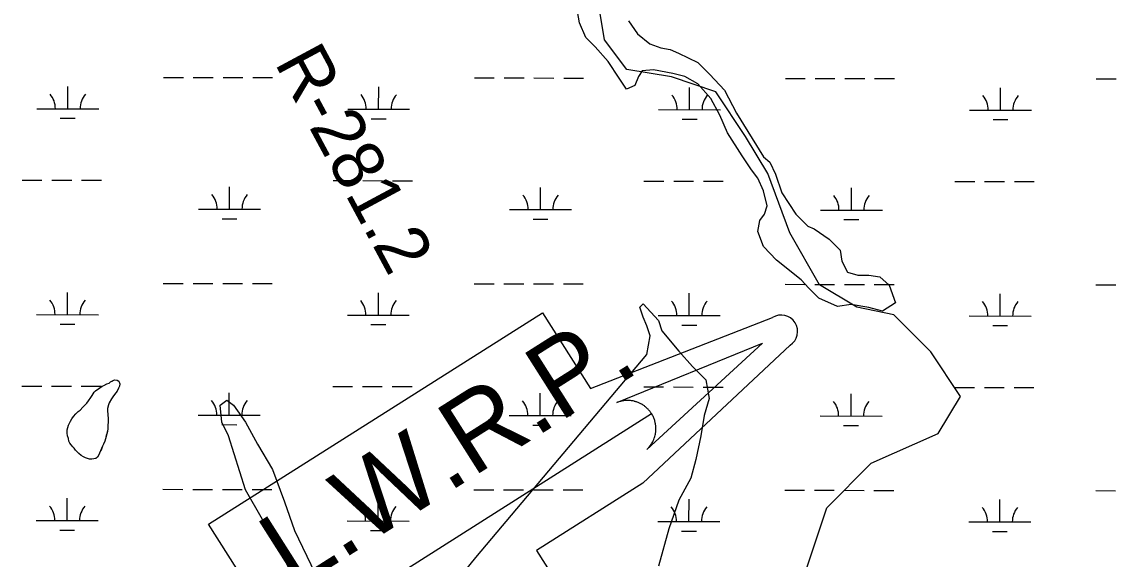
# Model space of a CAD drawing. Extents: x 3208593 to 3246461, y 812903 to 838290.
# Drawn here: x 3212819 to 3214585, y 827157 to 828025 of the extents above; entities that cross this region are included whole.
import ezdxf

# ---------------------------------------------------------------- set-up
doc = ezdxf.new("R2010")
doc.units = 0
for name, color, linetype in [('V-RIVR-RANG-IDEN', 7, 'Continuous'), ('V-SITE-VEGE', 7, 'Continuous'), ('V-TOPO-SHOR', 7, 'Continuous'), ('V-TOPO-WATR-IDEN', 7, 'Continuous'), ('V-WETL-SWMP', 7, 'Continuous')]:
    doc.layers.add(name, color=color, linetype=linetype)

msp = doc.modelspace()

# ---------------------------------------------------------------- linework, layer by layer
at = {"layer": 'V-SITE-VEGE'}
for p, q in [((3213718.7, 828023.5), (3213715.7, 828041.5)), ((3213729.1, 827999.7), (3213718.7, 828023.5)), ((3213797.8, 828026.5), (3213812.7, 828005.6)), ((3213812.7, 828005.6), (3213832.1, 827989.2)), ((3213744.1, 827984.7), (3213729.1, 827999.7)), ((3213832.1, 827989.2), (3213850, 827983.2)), ((3213765, 827960.8), (3213744.1, 827984.7)), ((3213850, 827983.2), (3213865, 827980.2)), ((3213865, 827980.2), (3213878.4, 827974.3)), ((3213878.4, 827974.3), (3213909.7, 827959.3)), ((3213782.9, 827934), (3213765, 827960.8)), ((3213909.7, 827959.3), (3213929.1, 827939.9)), ((3213814.2, 827936.9), (3213808.2, 827922)), ((3213820.2, 827945.9), (3213814.2, 827936.9)), ((3213838.1, 827947.4), (3213820.2, 827945.9)), ((3213869.4, 827941.4), (3213838.1, 827947.4)), ((3213888.8, 827936.9), (3213869.4, 827941.4)), ((3213909.7, 827925), (3213888.8, 827936.9)), ((3213929.1, 827939.9), (3213953, 827914.5)), ((3213794.8, 827916), (3213782.9, 827934)), ((3213808.2, 827922), (3213794.8, 827916)), ((3213930.6, 827901.1), (3213909.7, 827925)), ((3213945.5, 827874.2), (3213930.6, 827901.1)), ((3213953, 827914.5), (3213972.4, 827877.2)), ((3213957.5, 827845.9), (3213945.5, 827874.2)), ((3213972.4, 827877.2), (3214015.7, 827807)), ((3213981.4, 827808.5), (3213957.5, 827845.9)), ((3213996.3, 827786.1), (3213981.4, 827808.5)), ((3214015.7, 827807), (3214026.1, 827798.1)), ((3214026.1, 827798.1), (3214035.1, 827778.7)), ((3214006.7, 827772.7), (3213996.3, 827786.1)), ((3214035.1, 827778.7), (3214045.5, 827748.8)), ((3214015.7, 827751.8), (3214006.7, 827772.7)), ((3214021.7, 827727.9), (3214015.7, 827751.8)), ((3214045.5, 827748.8), (3214067.9, 827714.5)), ((3214017.2, 827714.5), (3214021.7, 827727.9)), ((3214009.7, 827704), (3214017.2, 827714.5)), ((3214067.9, 827714.5), (3214087.3, 827695)), ((3214006.7, 827686.1), (3214009.7, 827704)), ((3214087.3, 827695), (3214097.8, 827690.6)), ((3214097.8, 827690.6), (3214121.7, 827674.1)), ((3214015.7, 827662.2), (3214006.7, 827686.1)), ((3214121.7, 827674.1), (3214139.6, 827656.2)), ((3214036.6, 827639.8), (3214015.7, 827662.2)), ((3214139.6, 827656.2), (3214142.5, 827638.3)), ((3214076.9, 827608.4), (3214036.6, 827639.8)), ((3214142.5, 827638.3), (3214151.5, 827620.4)), ((3214151.5, 827620.4), (3214167.9, 827615.9)), ((3214088.8, 827595), (3214076.9, 827608.4)), ((3214167.9, 827615.9), (3214185.8, 827615.9)), ((3214185.8, 827615.9), (3214203.7, 827612.9)), ((3214203.7, 827612.9), (3214218.7, 827599.5)), ((3214218.7, 827599.5), (3214229.1, 827571.1)), ((3214105.2, 827578.6), (3214088.8, 827595)), ((3213816.4, 827564.1), (3213821.8, 827569.6)), ((3213821.8, 827547.7), (3213816.4, 827564.1)), ((3213821.8, 827569.6), (3213846.4, 827542.3)), ((3214135.1, 827565.1), (3214105.2, 827578.6)), ((3214157.5, 827568.1), (3214135.1, 827565.1)), ((3214185.8, 827563.6), (3214157.5, 827568.1)), ((3214208.2, 827557.7), (3214185.8, 827563.6)), ((3214229.1, 827571.1), (3214208.2, 827557.7)), ((3213827.3, 827534.1), (3213821.8, 827547.7)), ((3213832.7, 827517.6), (3213827.3, 827534.1)), ((3213846.4, 827542.3), (3213851.9, 827525.8)), ((3213827.3, 827487.6), (3213832.7, 827517.6)), ((3213851.9, 827525.8), (3213879.2, 827493)), ((3213879.2, 827493), (3213901.1, 827468.4)), ((3213551.3, 827159.5), (3213827.3, 827487.6)), ((3213901.1, 827468.4), (3213922.9, 827446.6)), ((3212951, 827437.5), (3212956, 827440.1)), ((3212956, 827440.1), (3212959.5, 827441.3)), ((3212959.5, 827441.3), (3212961.9, 827443.2)), ((3212961.9, 827443.2), (3212968, 827446.4)), ((3212968, 827446.4), (3212972.3, 827446.1)), ((3212972.3, 827446.1), (3212975.3, 827444.5)), ((3212975.3, 827444.5), (3212976.9, 827440.3)), ((3212976.9, 827440.3), (3212976.1, 827436.4)), ((3213922.9, 827446.6), (3213928.4, 827416.5)), ((3212932.3, 827421.4), (3212933.7, 827424.1)), ((3212933.7, 827424.1), (3212935.3, 827426.7)), ((3212935.3, 827426.7), (3212937.4, 827429.1)), ((3212937.4, 827429.1), (3212948.1, 827436.3)), ((3212948.1, 827436.3), (3212951, 827437.5)), ((3212972.4, 827428.5), (3212966.5, 827420.9)), ((3212974.8, 827433), (3212972.4, 827428.5)), ((3212976.1, 827436.4), (3212974.8, 827433)), ((3212917.2, 827402.3), (3212920.5, 827405.7)), ((3212920.5, 827405.7), (3212923.3, 827408.7)), ((3212923.3, 827408.7), (3212926.4, 827412.6)), ((3212926.4, 827412.6), (3212930.2, 827418)), ((3212930.2, 827418), (3212932.3, 827421.4)), ((3212958.5, 827406.3), (3212957.1, 827400.5)), ((3212959.5, 827409.6), (3212958.5, 827406.3)), ((3212963.2, 827416), (3212959.5, 827409.6)), ((3212966.5, 827420.9), (3212963.2, 827416)), ((3213138.7, 827405.6), (3213149.6, 827413.8)), ((3213141.4, 827378.2), (3213138.7, 827405.6)), ((3213149.6, 827413.8), (3213160.5, 827405.6)), ((3213160.5, 827405.6), (3213179.7, 827378.2)), ((3213928.4, 827416.5), (3213920.2, 827389.2)), ((3212899.5, 827383.8), (3212902.2, 827387.4)), ((3212902.2, 827387.4), (3212906, 827391.8)), ((3212906, 827391.8), (3212909.5, 827395.4)), ((3212909.5, 827395.4), (3212912.5, 827397.7)), ((3212912.5, 827397.7), (3212917.2, 827402.3)), ((3212957.1, 827400.5), (3212957.1, 827396)), ((3212957.1, 827396), (3212957.6, 827391)), ((3212957.6, 827391), (3212957.8, 827383.1)), ((3213920.2, 827389.2), (3213914.7, 827356.3)), ((3212892, 827366), (3212893.8, 827373.3)), ((3212893.8, 827373.3), (3212895.3, 827376.7)), ((3212895.3, 827376.7), (3212896.9, 827379.9)), ((3212896.9, 827379.9), (3212899.5, 827383.8)), ((3212957.6, 827373.2), (3212957.3, 827367.3)), ((3212957.8, 827378.2), (3212957.6, 827373.2)), ((3212957.8, 827383.1), (3212957.8, 827378.2)), ((3213152.4, 827356.3), (3213141.4, 827378.2)), ((3213179.7, 827378.2), (3213198.8, 827342.7)), ((3212891.7, 827360.3), (3212892, 827366)), ((3212892.3, 827356.3), (3212891.7, 827360.3)), ((3212893.9, 827351.8), (3212892.3, 827356.3)), ((3212894.7, 827347.6), (3212893.9, 827351.8)), ((3212953.6, 827351.5), (3212952.4, 827347.7)), ((3212956.9, 827363.9), (3212953.6, 827351.5)), ((3212957.3, 827367.3), (3212956.9, 827363.9)), ((3213179.7, 827268.9), (3213152.4, 827356.3)), ((3213914.7, 827356.3), (3213906.5, 827318.1)), ((3212895.9, 827344.5), (3212894.7, 827347.6)), ((3212898.1, 827341.5), (3212895.9, 827344.5)), ((3212900.7, 827338.2), (3212898.1, 827341.5)), ((3212902.8, 827336), (3212900.7, 827338.2)), ((3212905.4, 827333.1), (3212902.8, 827336)), ((3212948.9, 827339.4), (3212945.6, 827331.8)), ((3212950.3, 827342.9), (3212948.9, 827339.4)), ((3212952.4, 827347.7), (3212950.3, 827342.9)), ((3213198.8, 827342.7), (3213223.4, 827301.7)), ((3212910.6, 827327.5), (3212905.4, 827333.1)), ((3212914.4, 827324.4), (3212910.6, 827327.5)), ((3212918.1, 827322), (3212914.4, 827324.4)), ((3212921.5, 827320.5), (3212918.1, 827322)), ((3212924.7, 827319.5), (3212921.5, 827320.5)), ((3212927.8, 827318.7), (3212924.7, 827319.5)), ((3212931.8, 827318.3), (3212927.8, 827318.7)), ((3212934.9, 827318.8), (3212931.8, 827318.3)), ((3212938.1, 827319.6), (3212934.9, 827318.8)), ((3212940.5, 827321.7), (3212938.1, 827319.6)), ((3212942.8, 827325.5), (3212940.5, 827321.7)), ((3212944.2, 827328.3), (3212942.8, 827325.5)), ((3212945.6, 827331.8), (3212944.2, 827328.3)), ((3213906.5, 827318.1), (3213898.3, 827288)), ((3213223.4, 827301.7), (3213242.5, 827249.7)), ((3213898.3, 827288), (3213879.2, 827252.5)), ((3213234.3, 827173.2), (3213179.7, 827268.9)), ((3213242.5, 827249.7), (3213258.9, 827203.2)), ((3213879.2, 827252.5), (3213862.8, 827206)), ((3213258.9, 827203.2), (3213291.7, 827134.9)), ((3213862.8, 827206), (3213846.4, 827145.8)), ((3213267.1, 827107.6), (3213234.3, 827173.2)), ((3213442, 827025.5), (3213551.3, 827159.5))]:
    msp.add_line(p, q, dxfattribs=at)
at = {"layer": 'V-TOPO-SHOR'}
for points in [[(3214085.5, 827141.1), (3214117.9, 827240.1), (3214189.9, 827312), (3214297.9, 827359.8), (3214334, 827419.7), (3214286.1, 827491.7), (3214226.2, 827551.7), (3214166.3, 827563.8), (3214106.4, 827599.9), (3214058.5, 827683.9), (3214022.7, 827779.9), (3213986.8, 827839.9), (3213939, 827911.9), (3213867.1, 827936), (3213795.1, 827948.1), (3213759.2, 827996.1), (3213747.3, 828068)], [(3212944.5, 827433.9), (3212948.1, 827436.3), (3212951, 827437.5), (3212956, 827440.1), (3212959.5, 827441.3), (3212961.9, 827443.2), (3212964.6, 827444.6), (3212968, 827446.4), (3212972.3, 827446.1), (3212975.3, 827444.5), (3212976.9, 827440.3), (3212976.1, 827436.4), (3212974.8, 827433), (3212972.4, 827428.5), (3212970.3, 827425.7), (3212966.5, 827420.9), (3212963.2, 827416), (3212959.5, 827409.6), (3212958.5, 827406.3), (3212957.1, 827400.5), (3212957.1, 827396), (3212957.6, 827391), (3212957.8, 827383.1), (3212957.8, 827378.2), (3212957.6, 827373.2), (3212957.3, 827367.3), (3212956.9, 827363.9), (3212956.1, 827361), (3212954.9, 827356.8), (3212953.6, 827351.5), (3212952.4, 827347.7), (3212950.3, 827342.9), (3212948.9, 827339.4), (3212946.9, 827334.8), (3212945.6, 827331.8), (3212944.2, 827328.3), (3212942.8, 827325.5), (3212940.5, 827321.7), (3212938.1, 827319.6), (3212934.9, 827318.8), (3212931.8, 827318.3), (3212927.8, 827318.7), (3212924.7, 827319.5), (3212921.5, 827320.5), (3212918.1, 827322), (3212914.4, 827324.4), (3212910.6, 827327.5), (3212908.4, 827329.9), (3212905.4, 827333.1), (3212902.8, 827336), (3212900.7, 827338.2), (3212898.1, 827341.5), (3212895.9, 827344.5), (3212894.7, 827347.6), (3212893.9, 827351.8), (3212892.3, 827356.3), (3212891.7, 827360.3), (3212892, 827366), (3212893.8, 827373.3), (3212895.3, 827376.7), (3212896.9, 827379.9), (3212899.5, 827383.8), (3212902.2, 827387.4), (3212906, 827391.8), (3212909.5, 827395.4), (3212912.5, 827397.7), (3212917.2, 827402.3), (3212920.5, 827405.7), (3212923.3, 827408.7), (3212926.4, 827412.6), (3212930.2, 827418), (3212932.3, 827421.4), (3212933.7, 827424.1), (3212935.3, 827426.7), (3212937.4, 827429.1), (3212944.5, 827433.9)]]:
    msp.add_lwpolyline(points, dxfattribs=at)
at = {"layer": 'V-TOPO-WATR-IDEN'}
msp.add_line((3213200.6, 826989.8), (3213835.1, 827392.1), dxfattribs=at)
for points in [[(3212977, 826879.5), (3213197.3, 827091), (3213119.8, 827213.2), (3213659.1, 827555.1), (3213736.6, 827432.9), (3214030.3, 827547.2)], [(3214058.7, 827502.4), (3213821, 827279.9), (3213649.2, 827171), (3213732.4, 827039.8), (3213572.7, 826938.6), (3213489.6, 827069.8), (3213299.7, 826949.4), (3213005.4, 826834.7)]]:
    msp.add_lwpolyline(points, dxfattribs=at)
msp.add_lwpolyline([(3213779.3, 827410), (3214014.4, 827505.8), (3213827.5, 827334), (3213830.7, 827337.2), (3213833.4, 827340.7), (3213834.4, 827342.1), (3213835.3, 827343.4), (3213836.3, 827345.1), (3213837.1, 827346.7), (3213837.8, 827348.1), (3213838.7, 827350.1), (3213839.5, 827352.3), (3213840, 827353.5), (3213840.4, 827355.1), (3213841, 827357.3), (3213841.3, 827358.9), (3213841.7, 827360.8), (3213841.8, 827362), (3213842, 827363.3), (3213842.1, 827364.9), (3213842.2, 827366.4), (3213842.2, 827368), (3213842.1, 827369.2), (3213842, 827371), (3213841.9, 827372.8), (3213841.7, 827374.2), (3213841.4, 827375.8), (3213841.1, 827377.2), (3213840.9, 827378.4), (3213840.6, 827379.4), (3213840.2, 827380.8), (3213839.7, 827382.3), (3213839.2, 827383.7), (3213838.7, 827385.1), (3213838.1, 827386.3), (3213837.5, 827387.7), (3213836.9, 827388.8), (3213836.1, 827390.4), (3213835.1, 827392.1), (3213834.7, 827392.6), (3213834.2, 827393.4), (3213833.6, 827394.3), (3213832.9, 827395.1), (3213832.3, 827395.9), (3213831.7, 827396.7), (3213830.9, 827397.6), (3213830.3, 827398.3), (3213829.5, 827399.1), (3213828.7, 827400), (3213828.2, 827400.5), (3213826.7, 827401.9), (3213825.9, 827402.6), (3213825.3, 827403.1), (3213824.3, 827403.8), (3213823.5, 827404.5), (3213822.5, 827405.1), (3213821.4, 827405.9), (3213820.3, 827406.6), (3213819.5, 827407.1), (3213818.8, 827407.5), (3213817.8, 827408), (3213816.9, 827408.5), (3213815.8, 827409), (3213814.7, 827409.5), (3213813.5, 827410), (3213812.1, 827410.5), (3213811.1, 827410.9), (3213809.9, 827411.3), (3213808.7, 827411.6), (3213807.8, 827411.9), (3213806.8, 827412.1), (3213805.2, 827412.5), (3213805.2, 827412.5), (3213804.3, 827412.6), (3213803.6, 827412.8), (3213802.5, 827412.9), (3213801.3, 827413.1), (3213800.3, 827413.2), (3213799.3, 827413.2), (3213798.2, 827413.3), (3213797, 827413.3), (3213796.2, 827413.3), (3213795.1, 827413.3), (3213793.7, 827413.2), (3213792.8, 827413.2), (3213792.1, 827413.1), (3213791.5, 827413.1), (3213790.8, 827413), (3213789.8, 827412.8), (3213788.8, 827412.7), (3213787.9, 827412.5), (3213786.9, 827412.3), (3213785.7, 827412), (3213785, 827411.9), (3213783.8, 827411.6), (3213782.5, 827411.2), (3213781.5, 827410.8), (3213780.8, 827410.6), (3213780.1, 827410.3), (3213779.6, 827410.1)], close=True, dxfattribs=at)
msp.add_arc((3214044.5, 827524.8), 26.5, 302.3736, 122.3736, dxfattribs=at)
at = {"layer": 'V-WETL-SWMP'}
for p, q in [((3213047.4, 827935.1), (3213079.4, 827935.1)), ((3213095.4, 827935.1), (3213127.4, 827935)), ((3213143.4, 827935), (3213175.4, 827934.9)), ((3213191.4, 827934.9), (3213223.4, 827934.9)), ((3213549.3, 827934.4), (3213581.3, 827934.3)), ((3213597.3, 827934.3), (3213629.3, 827934.3)), ((3213645.3, 827934.3), (3213677.3, 827934.2)), ((3213693.3, 827934.2), (3213725.3, 827934.1)), ((3212892.7, 827884.6), (3212892.8, 827920.6)), ((3213394.6, 827883.9), (3213394.7, 827919.9)), ((3213896.5, 827883.1), (3213896.6, 827919.1)), ((3214051.2, 827933.7), (3214083.2, 827933.6)), ((3214099.2, 827933.6), (3214131.2, 827933.5)), ((3214147.2, 827933.5), (3214179.2, 827933.5)), ((3214195.2, 827933.5), (3214227.2, 827933.4)), ((3214398.4, 827882.4), (3214398.5, 827918.4)), ((3214553.1, 827932.9), (3214585.1, 827932.9)), ((3212842.7, 827884.7), (3212942.7, 827884.5)), ((3213344.6, 827883.9), (3213444.6, 827883.8)), ((3213846.5, 827883.2), (3213946.5, 827883.1)), ((3214348.4, 827882.5), (3214448.4, 827882.3)), ((3212880.7, 827869.2), (3212904.7, 827869.2)), ((3213382.6, 827868.5), (3213406.6, 827868.4)), ((3213884.5, 827867.7), (3213908.5, 827867.7)), ((3214386.4, 827867), (3214410.4, 827867)), ((3212819.1, 827769.3), (3212851.1, 827769.2)), ((3212867.1, 827769.2), (3212899.1, 827769.2)), ((3212915.1, 827769.1), (3212947.1, 827769.1)), ((3213153.9, 827722.4), (3213154, 827758.4)), ((3213321, 827768.6), (3213353, 827768.5)), ((3213369, 827768.5), (3213401, 827768.4)), ((3213417, 827768.4), (3213449, 827768.4)), ((3213655.8, 827721.6), (3213655.9, 827757.6)), ((3213822.9, 827767.8), (3213854.9, 827767.8)), ((3213870.9, 827767.8), (3213902.9, 827767.7)), ((3213918.9, 827767.7), (3213950.9, 827767.6)), ((3214324.8, 827767.1), (3214356.8, 827767)), ((3214372.8, 827767), (3214404.8, 827767)), ((3214420.8, 827767), (3214452.8, 827766.9)), ((3214157.7, 827720.9), (3214157.8, 827756.9)), ((3213103.9, 827722.4), (3213203.9, 827722.3)), ((3213141.9, 827707), (3213165.9, 827706.9)), ((3213605.8, 827721.7), (3213705.8, 827721.6)), ((3213643.8, 827706.2), (3213667.8, 827706.2)), ((3214107.7, 827721), (3214207.7, 827720.8)), ((3214145.7, 827705.5), (3214169.7, 827705.5)), ((3213046.9, 827602.4), (3213078.9, 827602.4)), ((3213094.9, 827602.4), (3213126.9, 827602.3)), ((3213142.9, 827602.3), (3213174.9, 827602.3)), ((3213190.9, 827602.2), (3213222.9, 827602.2)), ((3213548.8, 827601.7), (3213580.8, 827601.7)), ((3213596.8, 827601.6), (3213628.8, 827601.6)), ((3213644.8, 827601.6), (3213676.8, 827601.5)), ((3213692.8, 827601.5), (3213724.8, 827601.5)), ((3214050.7, 827601), (3214082.7, 827600.9)), ((3214098.7, 827600.9), (3214130.7, 827600.9)), ((3214146.7, 827600.8), (3214178.7, 827600.8)), ((3214194.7, 827600.8), (3214226.7, 827600.7)), ((3214552.6, 827600.3), (3214584.6, 827600.2)), ((3212892.2, 827551.9), (3212892.3, 827587.9)), ((3213394.1, 827551.2), (3213394.2, 827587.2)), ((3213896, 827550.5), (3213896.1, 827586.5)), ((3214397.9, 827549.7), (3214398, 827585.7)), ((3212842.2, 827552), (3212942.2, 827551.9)), ((3213344.1, 827551.3), (3213444.1, 827551.1)), ((3213846, 827550.5), (3213946, 827550.4)), ((3214347.9, 827549.8), (3214447.9, 827549.7)), ((3212880.2, 827536.5), (3212904.2, 827536.5)), ((3213382.1, 827535.8), (3213406.1, 827535.8)), ((3213884, 827535.1), (3213908, 827535)), ((3214385.9, 827534.3), (3214409.9, 827534.3)), ((3212951, 827437.5), (3212956, 827440.1)), ((3212956, 827440.1), (3212959.5, 827441.3)), ((3212959.5, 827441.3), (3212961.9, 827443.2)), ((3212961.9, 827443.2), (3212964.6, 827444.6)), ((3212964.6, 827444.6), (3212968, 827446.4)), ((3212968, 827446.4), (3212972.3, 827446.1)), ((3212972.3, 827446.1), (3212975.3, 827444.5)), ((3212975.3, 827444.5), (3212976.9, 827440.3)), ((3212976.9, 827440.3), (3212976.1, 827436.4)), ((3212818.6, 827436.6), (3212850.6, 827436.6)), ((3212866.6, 827436.5), (3212898.6, 827436.5)), ((3212914.6, 827436.5), (3212946.6, 827436.4)), ((3212932.3, 827421.4), (3212933.7, 827424.1)), ((3212933.7, 827424.1), (3212935.3, 827426.7)), ((3212935.3, 827426.7), (3212937.4, 827429.1)), ((3212937.4, 827429.1), (3212948.1, 827436.3)), ((3212948.1, 827436.3), (3212951, 827437.5)), ((3212970.3, 827425.7), (3212966.5, 827420.9)), ((3212972.4, 827428.5), (3212970.3, 827425.7)), ((3212974.8, 827433), (3212972.4, 827428.5)), ((3212976.1, 827436.4), (3212974.8, 827433)), ((3213153.4, 827389.7), (3213153.5, 827425.7)), ((3213320.5, 827435.9), (3213352.5, 827435.8)), ((3213368.5, 827435.8), (3213400.5, 827435.8)), ((3213416.5, 827435.7), (3213448.5, 827435.7)), ((3213655.3, 827389), (3213655.4, 827425)), ((3213822.5, 827435.1), (3213854.5, 827435.1)), ((3213870.5, 827435.1), (3213902.5, 827435)), ((3213918.5, 827435), (3213950.5, 827435)), ((3214157.2, 827388.2), (3214157.3, 827424.2)), ((3214324.4, 827434.4), (3214356.4, 827434.4)), ((3214372.4, 827434.3), (3214404.4, 827434.3)), ((3214420.4, 827434.3), (3214452.4, 827434.2)), ((3212917.2, 827402.3), (3212920.5, 827405.7)), ((3212920.5, 827405.7), (3212923.3, 827408.7)), ((3212923.3, 827408.7), (3212926.4, 827412.6)), ((3212926.4, 827412.6), (3212930.2, 827418)), ((3212930.2, 827418), (3212932.3, 827421.4)), ((3212958.5, 827406.3), (3212957.1, 827400.5)), ((3212959.5, 827409.6), (3212958.5, 827406.3)), ((3212963.2, 827416), (3212959.5, 827409.6)), ((3212966.5, 827420.9), (3212963.2, 827416)), ((3212899.5, 827383.8), (3212902.2, 827387.4)), ((3212902.2, 827387.4), (3212906, 827391.8)), ((3212906, 827391.8), (3212909.5, 827395.4)), ((3212909.5, 827395.4), (3212912.5, 827397.7)), ((3212912.5, 827397.7), (3212917.2, 827402.3)), ((3212957.1, 827400.5), (3212957.1, 827396)), ((3212957.1, 827396), (3212957.6, 827391)), ((3212957.6, 827391), (3212957.8, 827383.1)), ((3213103.4, 827389.8), (3213203.4, 827389.6)), ((3213605.3, 827389), (3213705.3, 827388.9)), ((3214107.2, 827388.3), (3214207.2, 827388.2)), ((3212892, 827366), (3212893.8, 827373.3)), ((3212893.8, 827373.3), (3212895.3, 827376.7)), ((3212895.3, 827376.7), (3212896.9, 827379.9)), ((3212896.9, 827379.9), (3212899.5, 827383.8)), ((3212957.6, 827373.2), (3212957.3, 827367.3)), ((3212957.8, 827378.2), (3212957.6, 827373.2)), ((3212957.8, 827383.1), (3212957.8, 827378.2)), ((3213141.4, 827374.3), (3213165.4, 827374.2)), ((3213643.3, 827373.5), (3213667.3, 827373.5)), ((3214145.2, 827372.8), (3214169.2, 827372.8)), ((3212891.7, 827360.3), (3212892, 827366)), ((3212892.3, 827356.3), (3212891.7, 827360.3)), ((3212893.9, 827351.8), (3212892.3, 827356.3)), ((3212894.7, 827347.6), (3212893.9, 827351.8)), ((3212953.6, 827351.5), (3212952.4, 827347.7)), ((3212954.9, 827356.8), (3212953.6, 827351.5)), ((3212956.1, 827361), (3212954.9, 827356.8)), ((3212956.9, 827363.9), (3212956.1, 827361)), ((3212957.3, 827367.3), (3212956.9, 827363.9)), ((3212895.9, 827344.5), (3212894.7, 827347.6)), ((3212898.1, 827341.5), (3212895.9, 827344.5)), ((3212900.7, 827338.2), (3212898.1, 827341.5)), ((3212902.8, 827336), (3212900.7, 827338.2)), ((3212905.4, 827333.1), (3212902.8, 827336)), ((3212946.9, 827334.8), (3212945.6, 827331.9)), ((3212948.9, 827339.4), (3212946.9, 827334.8)), ((3212950.3, 827342.9), (3212948.9, 827339.4)), ((3212952.4, 827347.7), (3212950.3, 827342.9)), ((3212908.4, 827329.9), (3212905.4, 827333.1)), ((3212910.6, 827327.5), (3212908.4, 827329.9)), ((3212914.4, 827324.4), (3212910.6, 827327.5)), ((3212918.1, 827322), (3212914.4, 827324.4)), ((3212921.5, 827320.5), (3212918.1, 827322)), ((3212924.7, 827319.5), (3212921.5, 827320.5)), ((3212927.8, 827318.7), (3212924.7, 827319.5)), ((3212931.8, 827318.3), (3212927.8, 827318.7)), ((3212934.9, 827318.8), (3212931.8, 827318.3)), ((3212938.1, 827319.6), (3212934.9, 827318.8)), ((3212940.5, 827321.7), (3212938.1, 827319.6)), ((3212942.8, 827325.5), (3212940.5, 827321.7)), ((3212944.2, 827328.3), (3212942.8, 827325.5)), ((3212945.6, 827331.9), (3212944.2, 827328.3)), ((3213046.4, 827269.8), (3213078.4, 827269.7)), ((3213094.4, 827269.7), (3213126.4, 827269.7)), ((3213142.4, 827269.6), (3213174.4, 827269.6)), ((3213190.4, 827269.6), (3213222.4, 827269.5)), ((3213548.3, 827269), (3213580.3, 827269)), ((3213596.3, 827269), (3213628.3, 827268.9)), ((3213644.3, 827268.9), (3213676.3, 827268.9)), ((3213692.3, 827268.8), (3213724.3, 827268.8)), ((3214050.2, 827268.3), (3214082.2, 827268.3)), ((3214098.2, 827268.2), (3214130.2, 827268.2)), ((3214146.2, 827268.2), (3214178.2, 827268.1)), ((3214194.2, 827268.1), (3214226.2, 827268.1)), ((3214552.1, 827267.6), (3214584.1, 827267.5)), ((3212891.7, 827219.3), (3212891.8, 827255.3)), ((3213393.6, 827218.5), (3213393.7, 827254.5)), ((3213895.5, 827217.8), (3213895.6, 827253.8)), ((3214397.5, 827217.1), (3214397.5, 827253.1)), ((3212841.7, 827219.3), (3212941.7, 827219.2)), ((3213343.6, 827218.6), (3213443.6, 827218.5)), ((3213845.5, 827217.9), (3213945.5, 827217.7)), ((3214347.5, 827217.1), (3214447.5, 827217)), ((3212879.7, 827203.8), (3212903.7, 827203.8)), ((3213381.6, 827203.1), (3213405.6, 827203.1)), ((3213883.5, 827202.4), (3213907.5, 827202.3)), ((3214385.4, 827201.7), (3214409.4, 827201.6))]:
    msp.add_line(p, q, dxfattribs=at)
for centre, start, end in [((3212837.5, 827885.2), 359.1448, 40.6885), ((3212947.9, 827885), 139.1448, 180.6885), ((3213339.4, 827884.4), 359.1448, 40.6885), ((3213449.9, 827884.3), 139.1448, 180.6885), ((3213841.3, 827883.7), 359.1448, 40.6885), ((3213951.8, 827883.5), 139.1448, 180.6885), ((3214343.2, 827883), 359.1448, 40.6885), ((3214453.7, 827882.8), 139.1448, 180.6885), ((3213098.7, 827722.9), 359.1448, 40.6885), ((3213209.1, 827722.8), 139.1448, 180.6885), ((3213600.6, 827722.2), 359.1448, 40.6885), ((3213711.1, 827722), 139.1448, 180.6885), ((3214102.5, 827721.5), 359.1448, 40.6885), ((3214213, 827721.3), 139.1448, 180.6885), ((3212837, 827552.5), 359.1448, 40.6885), ((3212947.5, 827552.3), 139.1448, 180.6885), ((3213338.9, 827551.8), 359.1448, 40.6885), ((3213449.4, 827551.6), 139.1448, 180.6885), ((3213840.8, 827551), 359.1448, 40.6885), ((3213951.3, 827550.9), 139.1448, 180.6885), ((3214342.7, 827550.3), 359.1448, 40.6885), ((3214453.2, 827550.1), 139.1448, 180.6885), ((3213098.2, 827390.2), 359.1448, 40.6885), ((3213208.7, 827390.1), 139.1448, 180.6885), ((3213600.1, 827389.5), 359.1448, 40.6885), ((3213710.6, 827389.4), 139.1448, 180.6885), ((3214102, 827388.8), 359.1448, 40.6885), ((3214212.5, 827388.6), 139.1448, 180.6885), ((3212836.5, 827219.8), 359.1448, 40.6885), ((3212947, 827219.7), 139.1448, 180.6885), ((3213338.4, 827219.1), 359.1448, 40.6885), ((3213448.9, 827218.9), 139.1448, 180.6885), ((3213840.3, 827218.4), 359.1448, 40.6885), ((3213950.8, 827218.2), 139.1448, 180.6885), ((3214342.2, 827217.6), 359.1448, 40.6885), ((3214452.7, 827217.5), 139.1448, 180.6885)]:
    msp.add_arc(centre, 35.2, start, end, dxfattribs=at)

# ---------------------------------------------------------------- texts
at = {"layer": 'V-RIVR-RANG-IDEN'}
msp.add_text('R-281.2', height=83, rotation=298.2789, dxfattribs=at).set_placement((3213225.7, 827959))
at = {"layer": 'V-TOPO-WATR-IDEN'}
msp.add_text('L.W.R.P.', height=124.5, rotation=32.3735, dxfattribs=at).set_placement((3213256.7, 827105.3))

doc.saveas('drawing.dxf')
